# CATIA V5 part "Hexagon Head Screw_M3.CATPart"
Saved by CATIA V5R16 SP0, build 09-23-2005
Part number: Hexagon_Head_Screw_M3
Material "Yellow Brass": density 8470 kg/m3, Young's modulus 1.05e+11 Pa, Poisson ratio 0.346, thermal expansion 2e-05 1/K
Bounding box of the stored display mesh (mm): x -2.836 to 2.836, y -2.836 to 2.836, z -13 to 0
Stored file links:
  C:\V5_education\CATIA Data\ASD\Power Transmission Gear Assembly\Assembly Data\Hexagon Head Screw_M3.CATPart
  F:\RCCAR\Project(MJ)\hexagon head screw.xls
  C:\Program Files\Dassault Systemes\B20\win_b64\startup\materials\Catalog.CATMaterial
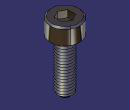
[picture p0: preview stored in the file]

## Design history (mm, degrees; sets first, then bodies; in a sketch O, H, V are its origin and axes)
External parameters (linked from other documents)
  External.d_Head = 5.68 mm
  External.K_Head_Height = 3 mm
  External.ds_Body = 3 mm
  External.Pitch = 0.5 mm
  External.lead = 10 mm
  External.v = 0.3 mm
  External.k = 0.6 mm
  External.t = 1.3 mm
  External.s = 2.56 mm
  `External.Bolt Type` = "M3"
Set1 "Reference Data"
  Point1 "Center Point": (0, 0, 0)
  Plane1: type Offset, RefPlane xy-plane, Offset 3 {= External.K_Head_Height}, reversed
Set2 "Helix Body"
  Helix1: Direction Z axis, RefPoint {point type Coord, X 0, Y 1.5 {= External.ds_Body /2}, Z -2 {= -External.K_Head_Height +1mm}}, Pitch 0.5 {= External.Pitch}, Height 20 {= External.lead +10mm}, TaperAngle 0
  Sweep1: type Segment, GuideCrv Helix1, Length1 0.5 {= External.Pitch}, Length2 0.2, Angle 60, DraftDirection xy-plane
  Sweep2: type Segment, GuideCrv Helix1, Length1 0.5 {= External.Pitch}, Length2 0.2, Angle 60, DraftDirection xy-plane
  Trim1: Trimmed (Sweep1; Sweep2)
  Split1: ToCut Trim1, Cutting Plane1
  Fill1: Boundary {boundary Boundary edge of Split1, Support Split1}
  Join1: Elements (Split1; Fill1)
Body1 (main body)
  Body2
    Sketch1 on yz-plane, origin (0, 0, 0), H (0, 1, 0), V (0, 0, 1)
      line L1 (2.84, -3) -> (2.84, 0)
      point P2 (2.84, 0)
      line L2 (2.84, 0) -> (0, 0)
      construction line L3 (0, 50.6222) -> (0, -71.272)
      point P3 (0, 50.6222)
      line L4 (2.84, -3) -> (0, -3)
      point P5 (0, -3)
      axis line L5 (0, 17.6953) -> (0, -27.6198)
      point P6 (0, 17.6953)
      reference intersected line E1 through (0, -3) direction (-1, 0) from Plane1
      distance L1 L3 = 2.84 {= External.d_Head /2}
      coincidence: P2 H, P3 V, P6 L3, E1 L4, P5 V
      vertical: L1 V, L3 V, L5 V
      horizontal: L2 H, L4 H
    Shaft1: profile Sketch1, axis Sketch1.L5, angle 360
    Chamfer1: length 0.3 {= External.v}, angle 45, on edge [face of Shaft1 from Sketch1.L2 | face of Shaft1 from Sketch1.L1]
    Body3
      Sketch2 on face of Shaft1 from Sketch1.L4, origin (0, 0, -3), H (1, 0, 0), V (0, -1, 0)
        circle A1 centre (0, 0) radius 1.5
        radius A1 = 1.5 {= External.ds_Body /2}
      Pad1: profile Sketch2, direction (0, 0, -1), length 10 {= External.lead}
      Chamfer2: length 0.6 {= External.k}, angle 45, on edge [face of Pad1 from Sketch2.A1 | end face of Pad1]
      Split2: SplitPlane Join1
    Assemble1: tool Body3
  Assemble2: tool Body2
  Body4
    Sketch3 on xy-plane, origin (0, 0, 0), H (1, 0, 0), V (0, 1, 0)
      point P1 (0, 0)
      point P2 (1.28, -0.739)
      point P3 (1.28, 0.739)
      point P4 (0, 1.478)
      point P5 (-1.28, 0.739)
      point P6 (-1.28, -0.739)
      point P7 (0, -1.478)
      point P8 (1.28, 0)
      line L1 (1.28, -0.739) -> (1.28, 0.739)
      line L2 (1.28, 0.739) -> (0, 1.478)
      line L3 (0, 1.478) -> (-1.28, 0.739)
      line L4 (-1.28, 0.739) -> (-1.28, -0.739)
      line L5 (-1.28, -0.739) -> (0, -1.478)
      line L6 (0, -1.478) -> (1.28, -0.739)
      construction line L7 (0, 0) -> (1.28, 0)
      construction circle A1 centre (0, 0) radius 1.478
      construction arc A2 centre (-1.28, -0.739) radius 1.478 from (-1.28, 0.739) to (0, -1.478) cw
      construction arc A3 centre (1.28, 0.739) radius 1.478 from (0, 1.478) to (1.28, -0.739) ccw
      distance L1 L4 = 2.56 {= External.s}
      coincidence: P1 V, A1 P2, A1 P3, A1 P4, A1 P5, A1 P6, A1 P7, A2 P1, A3 P1, H L7
      horizontal: L7 H
      midpoint: P8 L1
    Pocket1: profile Sketch3, direction (0, 0, -1), length 1.3 {= External.t}
  Remove1: tool Body4
Relations
  design table, configuration 4, drives External.d_Head, External.K_Head_Height, External.ds_Body, External.Pitch, External.lead, External.v, External.k, External.t, External.s (deactivated)
  rule:
    if `External.Bolt Type` =="M1.6"
    	{
    		External.d_Head =3.14mm
    		External.K_Head_Height =1.6mm
    		External.ds_Body =1.6mm
    		External.Pitch =0.35mm
    		External.lead =10mm
    		External.v=0.16mm
    		External.k =0.16mm
    		External.t =0.7mm
    		External.s =1.545mm
    	}
    else if `External.Bolt Type` =="M2"
    	{
    		External.d_Head =3.98mm
    		External.K_Head_Height =2mm
    		External.ds_Body =2mm
    		External.Pitch =0.4mm
    		External.lead =10mm
    		External.v=0.2mm
    		External.k =0.25mm
    		External.t =1mm
    		External.s =1.545mm
    	}
    else if `External.Bolt Type` =="M2.5"
    	{
    		External.d_Head =4.68mm
    		External.K_Head_Height =2.5mm
    		External.ds_Body =2.5mm
    		External.Pitch =0.45mm
    		External.lead =10mm
    		External.v=0.25mm
    		External.k =0.4mm
    		External.t =1.1mm
    		External.s=2.045mm
    	}
    else if `External.Bolt Type` =="M3"
    	{
    		External.d_Head =5.68mm
    		External.K_Head_Height =3mm
    		External.ds_Body =3mm
    		External.Pitch =0.5mm
    		External.lead =10mm
    		External.v=0.3mm
    		External.k =0.6mm
    		External.t =1.3mm
    		External.s=2.56mm
    	}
